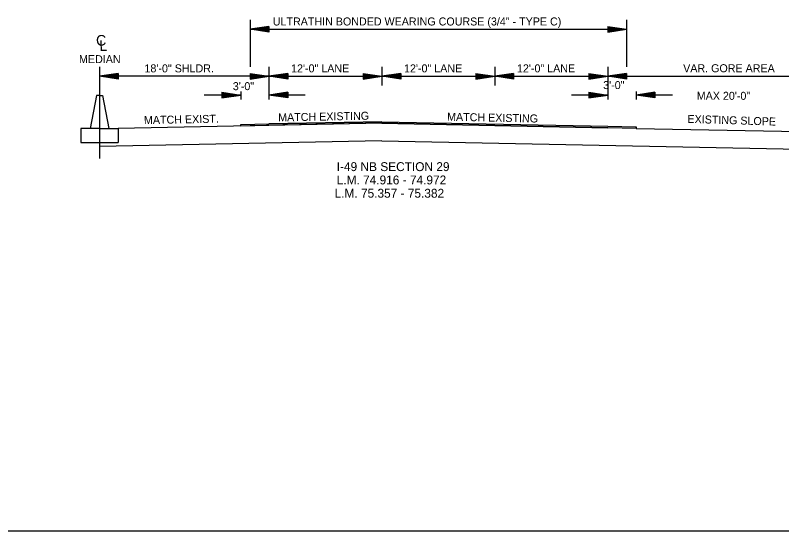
# Model space of a CAD drawing. Extents: x 2261938 to 2263136, y -3124572 to -3124216.
# Drawn here: x 2262179.8 to 2262261.2, y -3124556.1 to -3124501.3 of the extents above; entities that cross this region are included whole.
import ezdxf

# ---------------------------------------------------------------- set-up
doc = ezdxf.new("R2010")
doc.units = 0
for name, color, linetype in [('DSN_DRFT_Common-Annotations', 7, 'Continuous'), ('DSN_DRFT_Common-Line', 7, 'Continuous'), ('DSN_DRFT_Dimension', 7, 'Continuous')]:
    doc.layers.add(name, color=color, linetype=linetype)

msp = doc.modelspace()

# ---------------------------------------------------------------- linework, layer by layer
at = {"layer": 'DSN_DRFT_Common-Line'}
for p, q in [((2262204.758, -3124501.801), (2262204.758, -3124506.801)), ((2262244.758, -3124501.801), (2262244.758, -3124506.801)), ((2262188.758, -3124506.801), (2262188.758, -3124516.551)), ((2262206.758, -3124506.801), (2262206.758, -3124510.26)), ((2262218.758, -3124506.801), (2262218.758, -3124508.801)), ((2262230.758, -3124506.801), (2262230.758, -3124508.801)), ((2262242.758, -3124506.801), (2262242.758, -3124510.26)), ((2262188.425, -3124509.861), (2262187.758, -3124513.361)), ((2262188.758, -3124509.861), (2262188.425, -3124509.861)), ((2262188.758, -3124509.861), (2262189.092, -3124509.861)), ((2262189.092, -3124509.861), (2262189.758, -3124513.361)), ((2262203.758, -3124509.42), (2262203.758, -3124510.26)), ((2262245.758, -3124509.42), (2262245.758, -3124510.26)), ((2262218.758, -3124512.801), (2262190.758, -3124513.361)), ((2262218.758, -3124512.635), (2262206.758, -3124512.875)), ((2262218.758, -3124512.635), (2262242.758, -3124513.115)), ((2262218.758, -3124512.801), (2262242.758, -3124513.281)), ((2262245.758, -3124513.341), (2262245.758, -3124513.175)), ((2262186.758, -3124513.361), (2262186.758, -3124514.861)), ((2262188.758, -3124513.361), (2262186.758, -3124513.361)), ((2262188.758, -3124513.361), (2262190.758, -3124513.361)), ((2262190.758, -3124513.361), (2262190.758, -3124514.861)), ((2262245.758, -3124513.341), (2262266.758, -3124513.761)), ((2262218.758, -3124514.676), (2262188.758, -3124515.276)), ((2262218.758, -3124514.676), (2262305.582, -3124516.413)), ((2262186.758, -3124514.861), (2262190.758, -3124514.861))]:
    msp.add_line(p, q, dxfattribs=at)
for points in [[(2262153.708, -3124446.104), (2262153.708, -3124556.104), (2262323.708, -3124556.104), (2262323.708, -3124446.104)], [(2262242.758, -3124513.281), (2262218.758, -3124512.801), (2262206.758, -3124513.041), (2262203.758, -3124513.101), (2262203.758, -3124512.935), (2262206.758, -3124512.875), (2262218.758, -3124512.635), (2262242.758, -3124513.115), (2262245.758, -3124513.175), (2262245.758, -3124513.341)]]:
    msp.add_lwpolyline(points, close=True, dxfattribs=at)
at = {"layer": 'DSN_DRFT_Dimension'}
for p, q in [((2262206.758, -3124502.501), (2262204.758, -3124502.801)), ((2262206.758, -3124502.551), (2262205.092, -3124502.801)), ((2262206.758, -3124502.602), (2262205.436, -3124502.801)), ((2262206.758, -3124502.501), (2262206.758, -3124503.101)), ((2262242.758, -3124502.501), (2262244.758, -3124502.801)), ((2262242.758, -3124502.501), (2262242.758, -3124503.101)), ((2262242.758, -3124502.551), (2262244.424, -3124502.801)), ((2262242.758, -3124502.602), (2262244.08, -3124502.801)), ((2262206.758, -3124503.101), (2262204.758, -3124502.801)), ((2262204.758, -3124502.801), (2262244.758, -3124502.801)), ((2262206.758, -3124503.051), (2262205.092, -3124502.801)), ((2262206.758, -3124503), (2262205.436, -3124502.801)), ((2262206.758, -3124502.652), (2262205.769, -3124502.801)), ((2262206.758, -3124502.95), (2262205.769, -3124502.801)), ((2262206.758, -3124502.704), (2262206.108, -3124502.801)), ((2262206.758, -3124502.899), (2262206.108, -3124502.801)), ((2262206.758, -3124502.754), (2262206.442, -3124502.801)), ((2262206.758, -3124502.848), (2262206.442, -3124502.801)), ((2262242.758, -3124502.652), (2262243.747, -3124502.801)), ((2262242.758, -3124502.704), (2262243.408, -3124502.801)), ((2262242.758, -3124502.754), (2262243.074, -3124502.801)), ((2262242.758, -3124503.101), (2262244.758, -3124502.801)), ((2262242.758, -3124502.899), (2262243.408, -3124502.801)), ((2262242.758, -3124503), (2262244.08, -3124502.801)), ((2262242.758, -3124503.051), (2262244.424, -3124502.801)), ((2262242.758, -3124502.95), (2262243.747, -3124502.801)), ((2262242.758, -3124502.848), (2262243.074, -3124502.801)), ((2262190.758, -3124507.501), (2262188.758, -3124507.801)), ((2262206.758, -3124507.801), (2262188.758, -3124507.801)), ((2262190.758, -3124508.101), (2262188.758, -3124507.801)), ((2262190.758, -3124507.551), (2262189.092, -3124507.801)), ((2262190.758, -3124508.051), (2262189.092, -3124507.801)), ((2262190.758, -3124507.602), (2262189.436, -3124507.801)), ((2262190.758, -3124508), (2262189.436, -3124507.801)), ((2262190.758, -3124507.652), (2262189.769, -3124507.801)), ((2262190.758, -3124507.95), (2262189.769, -3124507.801)), ((2262190.758, -3124507.704), (2262190.108, -3124507.801)), ((2262190.758, -3124507.899), (2262190.108, -3124507.801)), ((2262190.758, -3124507.754), (2262190.442, -3124507.801)), ((2262190.758, -3124507.848), (2262190.442, -3124507.801)), ((2262190.758, -3124507.501), (2262190.758, -3124508.101)), ((2262204.758, -3124507.501), (2262206.758, -3124507.801)), ((2262204.758, -3124507.501), (2262204.758, -3124508.101)), ((2262204.758, -3124507.551), (2262206.424, -3124507.801)), ((2262204.758, -3124507.602), (2262206.08, -3124507.801)), ((2262204.758, -3124507.652), (2262205.747, -3124507.801)), ((2262204.758, -3124507.704), (2262205.408, -3124507.801)), ((2262204.758, -3124507.754), (2262205.074, -3124507.801)), ((2262204.758, -3124508.101), (2262206.758, -3124507.801)), ((2262204.758, -3124507.899), (2262205.408, -3124507.801)), ((2262204.758, -3124508), (2262206.08, -3124507.801)), ((2262204.758, -3124508.051), (2262206.424, -3124507.801)), ((2262204.758, -3124507.95), (2262205.747, -3124507.801)), ((2262204.758, -3124507.848), (2262205.074, -3124507.801)), ((2262208.758, -3124507.501), (2262206.758, -3124507.801)), ((2262206.758, -3124507.801), (2262218.758, -3124507.801)), ((2262208.758, -3124508.101), (2262206.758, -3124507.801)), ((2262208.758, -3124507.551), (2262207.092, -3124507.801)), ((2262208.758, -3124508.051), (2262207.092, -3124507.801)), ((2262208.758, -3124507.602), (2262207.436, -3124507.801)), ((2262208.758, -3124508), (2262207.436, -3124507.801)), ((2262208.758, -3124507.652), (2262207.769, -3124507.801)), ((2262208.758, -3124507.95), (2262207.769, -3124507.801)), ((2262208.758, -3124507.704), (2262208.108, -3124507.801)), ((2262208.758, -3124507.899), (2262208.108, -3124507.801)), ((2262208.758, -3124507.754), (2262208.442, -3124507.801)), ((2262208.758, -3124507.848), (2262208.442, -3124507.801)), ((2262208.758, -3124507.501), (2262208.758, -3124508.101)), ((2262216.758, -3124507.501), (2262218.758, -3124507.801)), ((2262216.758, -3124507.501), (2262216.758, -3124508.101)), ((2262216.758, -3124507.551), (2262218.424, -3124507.801)), ((2262216.758, -3124507.602), (2262218.08, -3124507.801)), ((2262216.758, -3124507.652), (2262217.747, -3124507.801)), ((2262216.758, -3124507.704), (2262217.408, -3124507.801)), ((2262216.758, -3124507.754), (2262217.074, -3124507.801)), ((2262216.758, -3124508.101), (2262218.758, -3124507.801)), ((2262216.758, -3124507.899), (2262217.408, -3124507.801)), ((2262216.758, -3124508), (2262218.08, -3124507.801)), ((2262216.758, -3124508.051), (2262218.424, -3124507.801)), ((2262216.758, -3124507.95), (2262217.747, -3124507.801)), ((2262216.758, -3124507.848), (2262217.074, -3124507.801)), ((2262220.758, -3124507.501), (2262218.758, -3124507.801)), ((2262218.758, -3124507.801), (2262230.758, -3124507.801)), ((2262220.758, -3124508.101), (2262218.758, -3124507.801)), ((2262220.758, -3124507.551), (2262219.092, -3124507.801)), ((2262220.758, -3124508.051), (2262219.092, -3124507.801)), ((2262220.758, -3124507.602), (2262219.436, -3124507.801)), ((2262220.758, -3124508), (2262219.436, -3124507.801)), ((2262220.758, -3124507.652), (2262219.769, -3124507.801)), ((2262220.758, -3124507.95), (2262219.769, -3124507.801)), ((2262220.758, -3124507.704), (2262220.108, -3124507.801)), ((2262220.758, -3124507.899), (2262220.108, -3124507.801)), ((2262220.758, -3124507.754), (2262220.442, -3124507.801)), ((2262220.758, -3124507.848), (2262220.442, -3124507.801)), ((2262220.758, -3124507.501), (2262220.758, -3124508.101)), ((2262228.758, -3124507.501), (2262230.758, -3124507.801)), ((2262228.758, -3124507.501), (2262228.758, -3124508.101)), ((2262228.758, -3124507.551), (2262230.424, -3124507.801)), ((2262228.758, -3124507.602), (2262230.08, -3124507.801)), ((2262228.758, -3124507.652), (2262229.747, -3124507.801)), ((2262228.758, -3124507.704), (2262229.408, -3124507.801)), ((2262228.758, -3124507.754), (2262229.074, -3124507.801)), ((2262228.758, -3124508.101), (2262230.758, -3124507.801)), ((2262228.758, -3124507.899), (2262229.408, -3124507.801)), ((2262228.758, -3124508), (2262230.08, -3124507.801)), ((2262228.758, -3124508.051), (2262230.424, -3124507.801)), ((2262228.758, -3124507.95), (2262229.747, -3124507.801)), ((2262228.758, -3124507.848), (2262229.074, -3124507.801)), ((2262232.758, -3124507.501), (2262230.758, -3124507.801)), ((2262230.758, -3124507.801), (2262242.758, -3124507.801)), ((2262232.758, -3124508.101), (2262230.758, -3124507.801)), ((2262232.758, -3124507.551), (2262231.092, -3124507.801)), ((2262232.758, -3124508.051), (2262231.092, -3124507.801)), ((2262232.758, -3124507.602), (2262231.436, -3124507.801)), ((2262232.758, -3124508), (2262231.436, -3124507.801)), ((2262232.758, -3124507.652), (2262231.769, -3124507.801)), ((2262232.758, -3124507.95), (2262231.769, -3124507.801)), ((2262232.758, -3124507.704), (2262232.108, -3124507.801)), ((2262232.758, -3124507.899), (2262232.108, -3124507.801)), ((2262232.758, -3124507.754), (2262232.442, -3124507.801)), ((2262232.758, -3124507.848), (2262232.442, -3124507.801)), ((2262232.758, -3124507.501), (2262232.758, -3124508.101)), ((2262240.758, -3124507.501), (2262242.758, -3124507.801)), ((2262240.758, -3124507.501), (2262240.758, -3124508.101)), ((2262240.758, -3124507.551), (2262242.424, -3124507.801)), ((2262240.758, -3124507.602), (2262242.08, -3124507.801)), ((2262240.758, -3124507.652), (2262241.747, -3124507.801)), ((2262240.758, -3124507.704), (2262241.408, -3124507.801)), ((2262240.758, -3124507.754), (2262241.074, -3124507.801)), ((2262240.758, -3124508.101), (2262242.758, -3124507.801)), ((2262240.758, -3124507.899), (2262241.408, -3124507.801)), ((2262240.758, -3124508), (2262242.08, -3124507.801)), ((2262240.758, -3124508.051), (2262242.424, -3124507.801)), ((2262240.758, -3124507.95), (2262241.747, -3124507.801)), ((2262240.758, -3124507.848), (2262241.074, -3124507.801)), ((2262244.758, -3124507.501), (2262242.758, -3124507.801)), ((2262242.758, -3124507.801), (2262267.758, -3124507.801)), ((2262244.758, -3124508.101), (2262242.758, -3124507.801)), ((2262244.758, -3124507.551), (2262243.092, -3124507.801)), ((2262244.758, -3124508.051), (2262243.092, -3124507.801)), ((2262244.758, -3124507.602), (2262243.436, -3124507.801)), ((2262244.758, -3124508), (2262243.436, -3124507.801)), ((2262244.758, -3124507.652), (2262243.769, -3124507.801)), ((2262244.758, -3124507.95), (2262243.769, -3124507.801)), ((2262244.758, -3124507.704), (2262244.108, -3124507.801)), ((2262244.758, -3124507.899), (2262244.108, -3124507.801)), ((2262244.758, -3124507.754), (2262244.442, -3124507.801)), ((2262244.758, -3124507.848), (2262244.442, -3124507.801)), ((2262244.758, -3124507.501), (2262244.758, -3124508.101)), ((2262203.758, -3124509.801), (2262199.893, -3124509.801)), ((2262201.758, -3124509.501), (2262203.758, -3124509.801)), ((2262201.758, -3124509.501), (2262201.758, -3124510.101)), ((2262201.758, -3124509.551), (2262203.424, -3124509.801)), ((2262201.758, -3124509.602), (2262203.08, -3124509.801)), ((2262201.758, -3124509.652), (2262202.747, -3124509.801)), ((2262201.758, -3124509.704), (2262202.408, -3124509.801)), ((2262201.758, -3124509.754), (2262202.074, -3124509.801)), ((2262201.758, -3124510.101), (2262203.758, -3124509.801)), ((2262201.758, -3124509.899), (2262202.408, -3124509.801)), ((2262201.758, -3124510), (2262203.08, -3124509.801)), ((2262201.758, -3124510.051), (2262203.424, -3124509.801)), ((2262201.758, -3124509.95), (2262202.747, -3124509.801)), ((2262201.758, -3124509.848), (2262202.074, -3124509.801)), ((2262208.758, -3124509.501), (2262206.758, -3124509.801)), ((2262208.758, -3124510.101), (2262206.758, -3124509.801)), ((2262210.623, -3124509.801), (2262206.758, -3124509.801)), ((2262208.758, -3124509.551), (2262207.092, -3124509.801)), ((2262208.758, -3124510.051), (2262207.092, -3124509.801)), ((2262208.758, -3124509.602), (2262207.436, -3124509.801)), ((2262208.758, -3124510), (2262207.436, -3124509.801)), ((2262208.758, -3124509.652), (2262207.769, -3124509.801)), ((2262208.758, -3124509.95), (2262207.769, -3124509.801)), ((2262208.758, -3124509.704), (2262208.108, -3124509.801)), ((2262208.758, -3124509.899), (2262208.108, -3124509.801)), ((2262208.758, -3124509.754), (2262208.442, -3124509.801)), ((2262208.758, -3124509.848), (2262208.442, -3124509.801)), ((2262208.758, -3124509.501), (2262208.758, -3124510.101)), ((2262242.758, -3124509.801), (2262238.893, -3124509.801)), ((2262240.758, -3124509.501), (2262242.758, -3124509.801)), ((2262240.758, -3124509.501), (2262240.758, -3124510.101)), ((2262240.758, -3124509.551), (2262242.424, -3124509.801)), ((2262240.758, -3124509.602), (2262242.08, -3124509.801)), ((2262240.758, -3124509.652), (2262241.747, -3124509.801)), ((2262240.758, -3124509.704), (2262241.408, -3124509.801)), ((2262240.758, -3124509.754), (2262241.074, -3124509.801)), ((2262240.758, -3124510.101), (2262242.758, -3124509.801)), ((2262240.758, -3124509.899), (2262241.408, -3124509.801)), ((2262240.758, -3124510), (2262242.08, -3124509.801)), ((2262240.758, -3124510.051), (2262242.424, -3124509.801)), ((2262240.758, -3124509.95), (2262241.747, -3124509.801)), ((2262240.758, -3124509.848), (2262241.074, -3124509.801)), ((2262247.758, -3124509.501), (2262245.758, -3124509.801)), ((2262247.758, -3124510.101), (2262245.758, -3124509.801)), ((2262249.623, -3124509.801), (2262245.758, -3124509.801)), ((2262247.758, -3124509.551), (2262246.092, -3124509.801)), ((2262247.758, -3124510.051), (2262246.092, -3124509.801)), ((2262247.758, -3124509.602), (2262246.436, -3124509.801)), ((2262247.758, -3124510), (2262246.436, -3124509.801)), ((2262247.758, -3124509.652), (2262246.769, -3124509.801)), ((2262247.758, -3124509.95), (2262246.769, -3124509.801)), ((2262247.758, -3124509.704), (2262247.108, -3124509.801)), ((2262247.758, -3124509.899), (2262247.108, -3124509.801)), ((2262247.758, -3124509.754), (2262247.442, -3124509.801)), ((2262247.758, -3124509.848), (2262247.442, -3124509.801)), ((2262247.758, -3124509.501), (2262247.758, -3124510.101))]:
    msp.add_line(p, q, dxfattribs=at)

# ---------------------------------------------------------------- texts
at = {"layer": 'DSN_DRFT_Common-Annotations'}
for s, height, p in [('ULTRATHIN BONDED WEARING COURSE (3/4" - TYPE C)', 0.85, (2262207.169, -3124502.406)), ('MEDIAN', 0.85, (2262186.582, -3124506.412)), ('18\'-0" SHLDR.', 0.85, (2262193.535, -3124507.391)), ('12\'-0" LANE', 0.85, (2262209.111, -3124507.391)), ('12\'-0" LANE', 0.85, (2262221.111, -3124507.391)), ('12\'-0" LANE', 0.85, (2262233.111, -3124507.391)), ('VAR. GORE AREA', 0.85, (2262250.768, -3124507.377)), (' 3\'-0"', 0.85, (2262241.952, -3124509.168)), (' 3\'-0"', 0.85, (2262202.603, -3124509.282)), ('MAX 20\'-0"', 0.85, (2262252.213, -3124510.307)), ('I-49 NB SECTION 29', 0.943, (2262213.962, -3124517.883)), ('L.M. 74.916 - 74.972', 0.943, (2262213.958, -3124519.298)), ('L.M. 75.357 - 75.382', 0.943, (2262213.735, -3124520.712))]:
    msp.add_text(s, height=height, dxfattribs=at).set_placement(p)
for s, height, rotation, p in [('C', 1.124, 1.14576, (2262188.401, -3124504.556)), ('L', 1.124, 1.14576, (2262188.751, -3124505.121)), ('MATCH EXISTING', 0.85, 1.14576, (2262207.748, -3124512.612)), ('MATCH EXIST.', 0.85, 1.14576, (2262193.488, -3124512.897)), ('MATCH EXISTING', 0.85, 358.85424, (2262225.68, -3124512.53)), ('EXISTING SLOPE', 0.85, 358.23112, (2262251.214, -3124512.758))]:
    msp.add_text(s, height=height, rotation=rotation, dxfattribs=at).set_placement(p)

doc.saveas('drawing.dxf')
